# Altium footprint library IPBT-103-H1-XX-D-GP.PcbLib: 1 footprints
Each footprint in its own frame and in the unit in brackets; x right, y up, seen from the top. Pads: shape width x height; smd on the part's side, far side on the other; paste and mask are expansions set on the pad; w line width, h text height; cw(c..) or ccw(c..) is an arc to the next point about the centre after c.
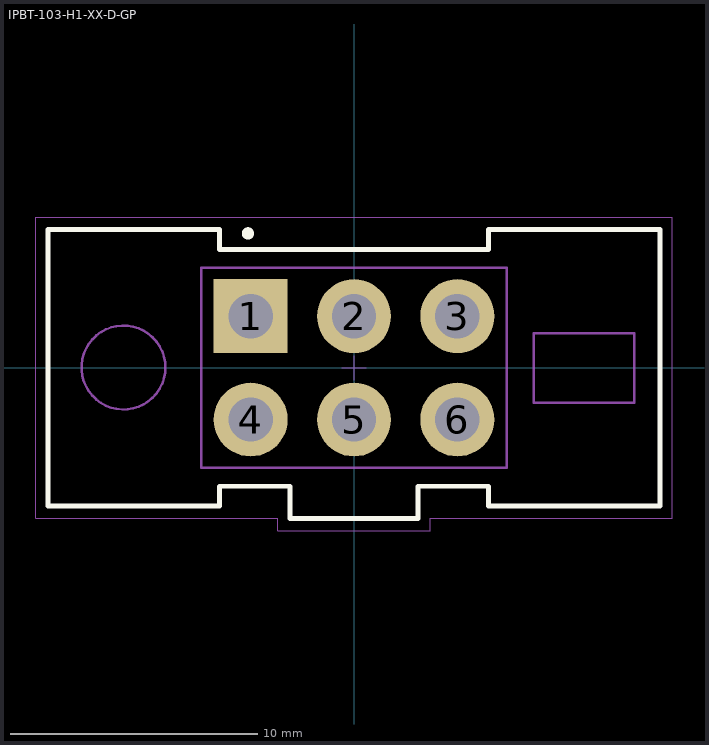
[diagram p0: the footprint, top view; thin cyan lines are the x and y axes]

## IPBT-103-H1-XX-D-GP [mm] "4.19mm pitch, power-mate header; double row"
height 10.29
pads (6):
  rect 3x3 / inner round 3 / far side rect 3x3 hole 1.8 mask+0: 1(-4.191,2.095)
  round 3 hole 1.8 mask+0: 2(0,2.095) 3(4.191,2.095) 4(-4.191,-2.096) 5(0,-2.096) 6(4.191,-2.096)
Top Overlay:
  circle w0.25: c-4.3,5.45 r0.125
  lines w0.2: -12.4,-5.6 -5.45,-5.6 -5.45,-4.8 -2.6,-4.8 -2.6,-6.1 2.6,-6.1 2.6,-4.8 5.45,-4.8 5.45,-5.6 12.4,-5.6 12.4,5.6 5.45,5.6 5.45,4.8 -5.45,4.8 -5.45,5.6 -12.4,5.6 -12.4,-5.6
Mechanical 12:
  lines w0.001: -12.4,-5.6 -5.45,-5.6 -5.45,-4.8 -2.6,-4.8 -2.6,-6.1 2.6,-6.1 2.6,-4.8 5.45,-4.8 5.45,-5.6 12.4,-5.6 12.4,5.6 5.45,5.6 5.45,4.8 -5.45,4.8 -5.45,5.6 -12.4,5.6 -12.4,-5.6
Mechanical 13:
  circle w0.1: c-9.347,0.012 r1.702
  lines w0.1: -12.4,-5.6 -5.45,-5.6 -5.45,-4.8 -2.6,-4.8 -2.6,-6.1 2.6,-6.1 2.6,-4.8 5.45,-4.8 5.45,-5.6 12.4,-5.6 12.4,5.6 5.45,5.6 5.45,4.8 -5.45,4.8 -5.45,5.6 -12.4,5.6 -12.4,-5.6 ; -6.198,-4.052 6.198,-4.052 6.198,4.051 -6.198,4.051 -6.198,-4.052 ; 7.29,-1.41 11.354,-1.41 11.354,1.409 7.29,1.409 7.29,-1.41
  text ".Designator" at 0.254,0.254 h1.52
Mechanical 15:
  lines w0.05: -0.5,0 0.5,0 ; 0,-0.5 0,0.5 ; -12.9,-6.1 -3.1,-6.1 -3.1,-6.6 3.1,-6.6 3.1,-6.1 12.9,-6.1 12.9,6.1 -12.9,6.1 -12.9,-6.1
